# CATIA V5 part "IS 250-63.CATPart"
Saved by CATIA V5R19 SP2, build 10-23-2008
Part number: IS 250-63
Bounding box of the stored display mesh (mm): x -18.951 to 18.951, y -18.952 to 18.952, z 0 to 176.999
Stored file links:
  C:\Users\Bora\Desktop\3D Katı model\IS serisi\IS 250\IS 250-63.CATPart
  C:\Program Files\Dassault Systemes\B19\intel_a\reffiles\standard\MetricThickPitch.txt
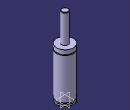
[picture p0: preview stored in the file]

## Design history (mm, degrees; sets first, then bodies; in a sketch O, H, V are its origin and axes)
Body1 (main body)
  Sketch1 on yz-plane, origin (0, 0, 0), H (0, 1, 0), V (0, 0, 1)
    point P3 (7.4677, 175.9995)
    point P5 (7.4677, 175.9995)
    point P7 (18.9677, 102.4995)
    point P8 (18.9677, 100.4995)
    point P12 (18.9677, 100.4995)
    point P13 (18.9677, 102.4995)
    line L1 (19, 0) -> (19, 4)
    line L2 (7.4677, 175.9995) -> (7.4677, 111.9995)
    arc A1 centre (6.4677, 175.9995) radius 1 from (7.4677, 175.9995) to (6.4677, 176.9995) ccw
    arc A2 centre (18.9677, 101.4995) radius 1 from (18.9677, 102.4995) to (18.9677, 100.4995) ccw
    line L3 (16.5, 7.5) -> (16.5, 4)
    line L4 (19, 7.5) -> (18.9677, 100.4995)
    line L5 (18.9677, 102.4995) -> (18.9677, 111.9995)
    line L6 (6.4677, 176.9995) -> (0, 176.9995)
    point P15 (0, 176.9995)
    line L7 (7.4677, 111.9995) -> (18.9677, 111.9995)
    line L8 (0, 0) -> (19, 0)
    line L9 (16.5, 4) -> (19, 4)
    line L10 (16.5, 7.5) -> (19, 7.5)
    coincidence: P15 V, P3 P5, P7 P13, P8 P12
    tangency: L6 A1
    horizontal: L7 H, L8 H, L9 H, L10 H
  Shaft1: profile Sketch1, axis Sketch1.V, angle 360
  Sketch2 on face of Shaft1 from Sketch1.L8, origin (0, 0, 0), H (1, 0, 0), V (0, -1, 0)
    point P1 (0, 0)
  Hole1: placed by Sketch2, at (0, 0, 0) direction (0, 0, 1), diameter 6.647, depth 7, threaded "M8", thread diameter 8, thread depth 7, pitch 1.25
